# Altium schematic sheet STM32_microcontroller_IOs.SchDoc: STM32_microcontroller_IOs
size A3; DocumentNumber: MB1312; Revision: A-03; SheetNumber: 3; SheetTotal: 9; Project: NUCLEO-L4P5ZG
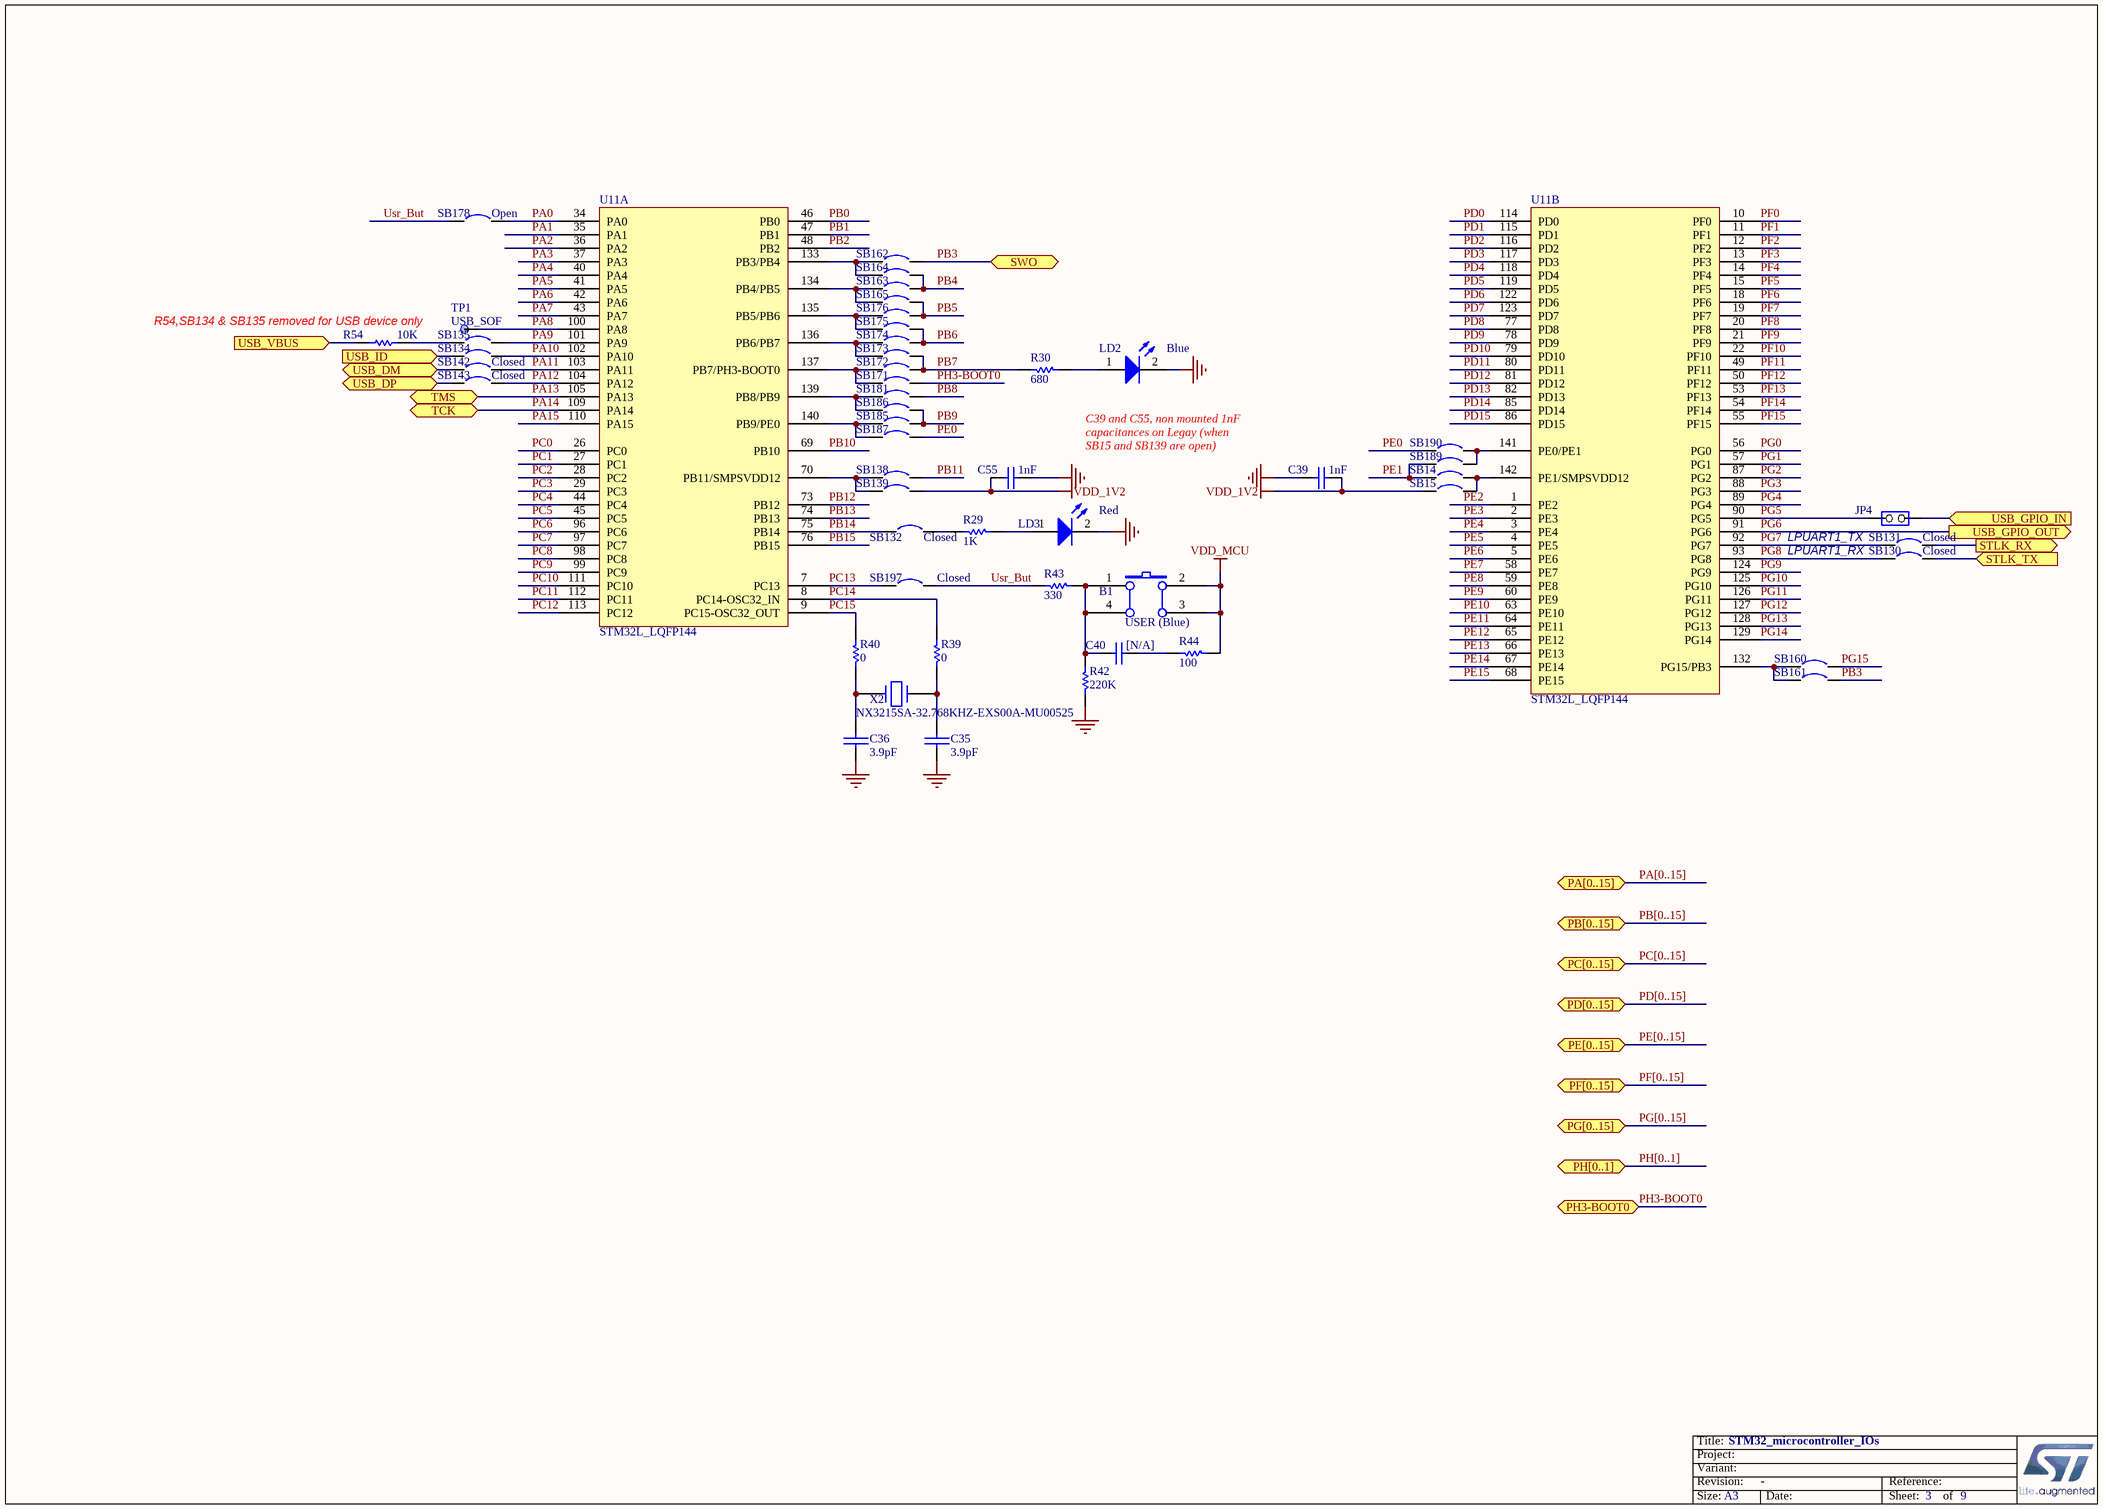
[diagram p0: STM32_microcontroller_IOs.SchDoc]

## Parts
B1  USER (Blue)  [PB-6X6mm-Blue]
C35  3.9pF  [0603C]
C36  3.9pF  [0603C]
C39  1nF  [0603C]
C40  [N/A]  [0603C]
C55  1nF  [0603C]
JP4  (no value)  [HDR_1x2_2R54_V_M_S]
LD2  Blue  [0603D-B]
LD3  Red  [0603D-R]
R29  1K  [0603R]
R30  680  [0603R]
R39  0  [0603R]
R40  0  [0603R]
R42  220K  [0603R]
R43  330  [0603R]
R44  100  [0603R]
R54  10K  [0603R]
SB14  Circuit Breaker  [SB_0603]  (value not drawn)
SB15  Circuit Breaker  [SB_0603]  (value not drawn)
SB130  Closed  [SB_0603]
SB131  Closed  [SB_0603]
SB132  Closed  [SB_0603]
SB134  Circuit Breaker  [SB_0603]  (value not drawn)
SB135  Circuit Breaker  [SB_0603]  (value not drawn)
SB138  Circuit Breaker  [SB_0603]  (value not drawn)
SB139  Circuit Breaker  [SB_0603]  (value not drawn)
SB142  Closed  [SB_0603]
SB143  Closed  [SB_0603]
SB160  Circuit Breaker  [SB_0603]  (value not drawn)
SB161  Circuit Breaker  [SB_0603]  (value not drawn)
SB162  Circuit Breaker  [SB_0603]  (value not drawn)
SB163  Circuit Breaker  [SB_0603]  (value not drawn)
SB164  Circuit Breaker  [SB_0603]  (value not drawn)
SB165  Circuit Breaker  [SB_0603]  (value not drawn)
SB171  Circuit Breaker  [SB_0603]  (value not drawn)
SB172  Circuit Breaker  [SB_0603]  (value not drawn)
SB173  Circuit Breaker  [SB_0603]  (value not drawn)
SB174  Circuit Breaker  [SB_0603]  (value not drawn)
SB175  Circuit Breaker  [SB_0603]  (value not drawn)
SB176  Circuit Breaker  [SB_0603]  (value not drawn)
SB178  Open  [SB_0603]
SB181  Circuit Breaker  [SB_0603]  (value not drawn)
SB185  Circuit Breaker  [SB_0603]  (value not drawn)
SB186  Circuit Breaker  [SB_0603]  (value not drawn)
SB187  Circuit Breaker  [SB_0603]  (value not drawn)
SB189  Circuit Breaker  [SB_0603]  (value not drawn)
SB190  Circuit Breaker  [SB_0603]  (value not drawn)
SB197  Closed  [SB_0603]
TP1  USB_SOF  [TP]
U11  STM32L_LQFP144  [LQFP144_0R5_SKT]  (parts A,B of 3)
X2  NX3215SA-32.768KHZ-EXS00A-MU00525  [XTAL_2SM_3R2X1R5]

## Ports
PA[0..15] (bidir), PB[0..15] (bidir), PC[0..15] (bidir), PD[0..15] (bidir), PE[0..15] (bidir), PF[0..15] (bidir), PG[0..15] (bidir), PH3-BOOT0, PH[0..1] (bidir), STLK_RX (out), STLK_TX (in), SWO, TCK, TMS, USB_DM (bidir), USB_DP (bidir), USB_GPIO_IN (in), USB_GPIO_OUT (out), USB_ID (in), USB_VBUS (in)

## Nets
GND: C35.2 C36.2 C39.1 C55.1 LD2.2(K) LD3.2(K) R42.2
VDD_1V2: C39.2 C55.2 SB15.2 SB139.2
VDD_MCU: B1.2(B0) B1.3(B1) R44.1
PA0: SB178.2 U11.34(PA0)
PA1: U11.35(PA1)
PA2: U11.36(PA2)
PA3: U11.37(PA3)
PA4: U11.40(PA4)
PA5: U11.41(PA5)
PA6: U11.42(PA6)
PA7: U11.43(PA7)
PA8: TP1.1 U11.100(PA8)
PA9: SB135.2 U11.101(PA9)
PA10: SB134.2 U11.102(PA10)
PA11: SB142.2 U11.103(PA11)
PA12: SB143.2 U11.104(PA12)
PA13: U11.105(PA13) ; port TMS
PA14: U11.109(PA14) ; port TCK
PA15: U11.110(PA15)
PB0: U11.46(PB0)
PB1: U11.47(PB1)
PB2: U11.48(PB2)
PB3: SB161.2 SB162.2 ; port SWO
PB4: SB163.2 SB164.2
PB5: SB165.2 SB176.2
PB6: SB174.2 SB175.2
PB7: R30.1 SB172.2 SB173.2
PB8: SB181.2
PB9: SB185.2 SB186.2
PB10: U11.69(PB10)
PB11: SB138.2
PB12: U11.73(PB12)
PB13: U11.74(PB13)
PB14: SB132.1 U11.75(PB14)
PB15: U11.76(PB15)
PC0: U11.26(PC0)
PC1: U11.27(PC1)
PC2: U11.28(PC2)
PC3: U11.29(PC3)
PC4: U11.44(PC4)
PC5: U11.45(PC5)
PC6: U11.96(PC6)
PC7: U11.97(PC7)
PC8: U11.98(PC8)
PC9: U11.99(PC9)
PC10: U11.111(PC10)
PC11: U11.112(PC11)
PC12: U11.113(PC12)
PC13: SB197.1 U11.7(PC13)
PC14: R39.2 U11.8(PC14-OSC32_IN)
PC15: R40.2 U11.9(PC15-OSC32_OUT)
PD0: U11.114(PD0)
PD1: U11.115(PD1)
PD2: U11.116(PD2)
PD3: U11.117(PD3)
PD4: U11.118(PD4)
PD5: U11.119(PD5)
PD6: U11.122(PD6)
PD7: U11.123(PD7)
PD8: U11.77(PD8)
PD9: U11.78(PD9)
PD10: U11.79(PD10)
PD11: U11.80(PD11)
PD12: U11.81(PD12)
PD13: U11.82(PD13)
PD14: U11.85(PD14)
PD15: U11.86(PD15)
PE0: SB187.2 SB190.1
PE1: SB14.1 SB189.1
PE2: U11.1(PE2)
PE3: U11.2(PE3)
PE4: U11.3(PE4)
PE5: U11.4(PE5)
PE6: U11.5(PE6)
PE7: U11.58(PE7)
PE8: U11.59(PE8)
PE9: U11.60(PE9)
PE10: U11.63(PE10)
PE11: U11.64(PE11)
PE12: U11.65(PE12)
PE13: U11.66(PE13)
PE14: U11.67(PE14)
PE15: U11.68(PE15)
PF0: U11.10(PF0)
PF1: U11.11(PF1)
PF2: U11.12(PF2)
PF3: U11.13(PF3)
PF4: U11.14(PF4)
PF5: U11.15(PF5)
PF6: U11.18(PF6)
PF7: U11.19(PF7)
PF8: U11.20(PF8)
PF9: U11.21(PF9)
PF10: U11.22(PF10)
PF11: U11.49(PF11)
PF12: U11.50(PF12)
PF13: U11.53(PF13)
PF14: U11.54(PF14)
PF15: U11.55(PF15)
PG0: U11.56(PG0)
PG1: U11.57(PG1)
PG2: U11.87(PG2)
PG3: U11.88(PG3)
PG4: U11.89(PG4)
PG5: JP4.2(NO) U11.90(PG5)
PG6: U11.91(PG6) ; port USB_GPIO_OUT
PG7: SB131.1 U11.92(PG7)
PG8: SB130.1 U11.93(PG8)
PG9: U11.124(PG9)
PG10: U11.125(PG10)
PG11: U11.126(PG11)
PG12: U11.127(PG12)
PG13: U11.128(PG13)
PG14: U11.129(PG14)
PG15: SB160.2
PH3-BOOT0: SB171.2 ; port PH3-BOOT0
STLK_RX: SB131.2 ; port STLK_RX
STLK_TX: SB130.2 ; port STLK_TX
USB_DM: SB142.1 ; port USB_DM
USB_DP: SB143.1 ; port USB_DP
USB_GPIO_IN: JP4.1(COMMON) ; port USB_GPIO_IN
USB_ID: SB134.1 ; port USB_ID
USB_VBUS: R54.1 ; port USB_VBUS
Usr_But: R43.2 SB178.1 SB197.2
NetB1_1: B1.1(A0) B1.4(A1) C40.2 R42.1 R43.1
NetC35_1: C35.1 R39.1 X2.2
NetC36_1: C36.1 R40.1 X2.1
NetC40_1: C40.1 R44.2
NetLD2_1: LD2.1(A) R30.2
NetLD3_1: LD3.1(A) R29.2
NetR29_1: R29.1 SB132.2
NetR54_2: R54.2 SB135.1
NetSB14_2: SB14.2 SB15.1 U11.142(PE1/SMPSVDD12)
NetSB138_1: SB138.1 SB139.1 U11.70(PB11/SMPSVDD12)
NetSB160_1: SB160.1 SB161.1 U11.132(PG15/PB3)
NetSB162_1: SB162.1 SB164.1 U11.133(PB3/PB4)
NetSB163_1: SB163.1 SB165.1 U11.134(PB4/PB5)
NetSB171_1: SB171.1 SB172.1 U11.137(PB7/PH3-BOOT0)
NetSB173_1: SB173.1 SB174.1 U11.136(PB6/PB7)
NetSB175_1: SB175.1 SB176.1 U11.135(PB5/PB6)
NetSB181_1: SB181.1 SB186.1 U11.139(PB8/PB9)
NetSB185_1: SB185.1 SB187.1 U11.140(PB9/PE0)
NetSB189_2: SB189.2 SB190.2 U11.141(PE0/PE1)

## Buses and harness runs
bus PA[0..15] = port PA[0..15]
bus PB[0..15] = port PB[0..15]
bus PC[0..15] = port PC[0..15]
bus PD[0..15] = port PD[0..15]
bus PE[0..15] = port PE[0..15]
bus PF[0..15] = port PF[0..15]
bus PG[0..15] = port PG[0..15]
bus PH[0..1] = port PH[0..1]

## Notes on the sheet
- (near R54) R54,SB134 & SB135 removed for USB device only
- C39 and C55, non mounted 1nF capacitances on Legay (when SB15 and SB139 are open)
- LPUART1_TX
- LPUART1_RX

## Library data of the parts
B1 = SW PUSHBUTTON: SE PUSHBUTTON
C35 C36 = CAP: Capacitor
C39 C55 = Cap: Capacitor; Value: 10nF
C40 = CAP: Capacitor; Value: 100pF
JP4 = JP2
LD2 LD3 = LED2: Typical RED, GREEN, YELLOW, AMBER GaAs LED
R29 = Res1: Resistor
R30 R39 R40 R43 R44 = Res1: Resistor; Value: 1K
R42 = res1: Resistor; Value: 1K
R54 = Resistor_ST: Resistor 0402 / 0603 / 0805
SB14 SB15 SB134 SB135 SB138 SB139 SB160-SB165 SB171-SB176 SB181 SB185-SB187 SB189 SB190 = Circuit Breaker: Solder: NO
SB130-SB132 SB142 SB143 SB197 = Circuit Breaker_close: Circuit Breaker
SB178 = Circuit Breaker
TP1 = TP
X2 = CRYSTAL_32K: Crystal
